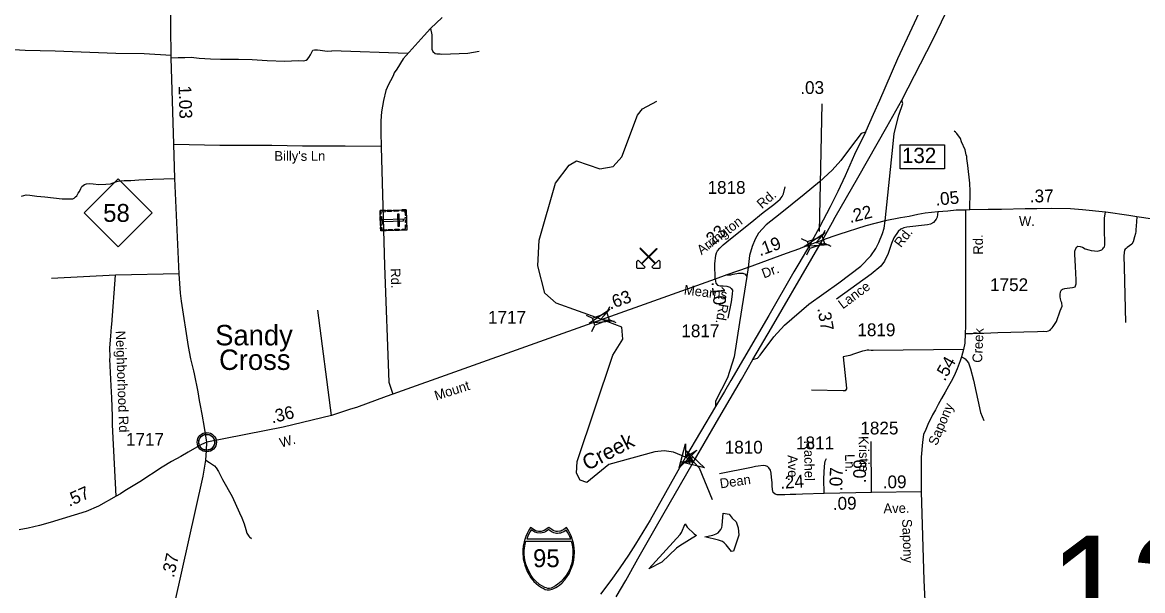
# Model space of a CAD drawing. Extents: x 2220236 to 2384410, y 720751 to 894131.
# Drawn here: x 2310413 to 2321364, y 782328 to 787885 of the extents above; entities that cross this region are included whole.
import ezdxf

# ---------------------------------------------------------------- set-up
doc = ezdxf.new("R2010")
doc.units = 0
doc.layers.add('Default', color=7, linetype='Continuous')

msp = doc.modelspace()

# ---------------------------------------------------------------- linework, layer by layer
at = {"layer": 'Default'}
for p, q in [((2314179, 787582), (2313439, 787606)), ((2318204, 785839), (2318230, 787089)), ((2318231, 785790), (2318262, 785853)), ((2318027, 785771), (2318089, 785741)), ((2318254, 785725), (2318316, 785695)), ((2318082, 785612), (2318112, 785674)), ((2311323, 785414), (2310698, 785381)), ((2311946, 785426), (2311323, 785414)), ((2313436, 784041), (2313303, 785071)), ((2316127, 785043), (2316157, 785105)), ((2315923, 785021), (2315985, 784992)), ((2316151, 784978), (2316214, 784949)), ((2315980, 784863), (2316009, 784925)), ((2318714, 783287), (2318709, 783787)), ((2316921, 783591), (2316944, 783632)), ((2316930, 783640), (2316928, 783659)), ((2316957, 783625), (2316974, 783633)), ((2316890, 783590), (2316907, 783598)), ((2316937, 783564), (2316935, 783583)), ((2319198, 783295), (2318714, 783287)), ((2318714, 783287), (2318252, 783279))]:
    msp.add_line(p, q, dxfattribs=at)
for points in [[(2321136, 791538), (2321055, 791411), (2321030, 791371), (2320819, 791034), (2320553, 790587), (2320307, 790180), (2320046, 789739), (2319894, 789466), (2319698, 789092), (2319507, 788713), (2319271, 788179), (2318968, 787528), (2318793, 787120), (2318731, 786983), (2318659, 786822), (2318654, 786812)], [(2319011, 787125), (2319317, 787721), (2319561, 788233), (2319957, 789028), (2320261, 789629), (2320682, 790477), (2320984, 791079), (2321067, 791240), (2321145, 791392)], [(2312216, 783779), (2312192, 783922), (2312170, 784052), (2312156, 784138), (2312146, 784186), (2312130, 784271), (2312096, 784447), (2312088, 784476), (2312061, 784594), (2312038, 784714), (2311969, 785157), (2311960, 785237), (2311946, 785426), (2311904, 786359), (2311894, 786693), (2311869, 787539), (2311869, 787562), (2311848, 789169)], [(2314518, 787933), (2314403, 787824), (2314342, 787757), (2314222, 787626), (2314137, 787527), (2314073, 787429), (2314048, 787392), (2314039, 787362), (2314012, 787312), (2313993, 787276), (2313966, 787220), (2313944, 787122), (2313923, 787009), (2313916, 786923), (2313916, 786815), (2313920, 786665), (2313952, 785508), (2313995, 784366), (2314036, 784250)], [(2314403, 787824), (2314416, 787762), (2314417, 787622), (2314427, 787599), (2314450, 787580), (2314464, 787577), (2314498, 787577), (2314512, 787575), (2314767, 787585), (2314877, 787605)], [(2311869, 787562), (2311604, 787576), (2311326, 787582), (2310733, 787602), (2310440, 787609), (2310276, 787620)], [(2311869, 787539), (2311937, 787541), (2312002, 787543), (2312062, 787545), (2312143, 787534), (2312253, 787528), (2312351, 787524), (2312525, 787526), (2312661, 787522), (2312806, 787511), (2312980, 787505), (2313110, 787511), (2313161, 787509), (2313188, 787515), (2313201, 787526), (2313214, 787541), (2313229, 787568), (2313245, 787600), (2313254, 787613), (2313269, 787617), (2313299, 787617), (2313324, 787613), (2313394, 787602), (2313439, 787606)], [(2317158, 783215), (2317033, 783526), (2316974, 783586), (2316932, 783611), (2316894, 783634), (2316777, 783682), (2316688, 783694), (2316597, 783686), (2316146, 783561), (2315932, 783384), (2315865, 783408), (2315831, 783475), (2315838, 783591), (2316185, 784629), (2316283, 784787), (2316273, 784905), (2316069, 784984), (2315630, 785138), (2315520, 785238), (2315451, 785505), (2315465, 785755), (2315625, 786312), (2315757, 786488), (2315831, 786531), (2316057, 786452), (2316190, 786477), (2316272, 786569), (2316426, 786979), (2316475, 787040), (2316616, 787114)], [(2318236, 785755), (2318333, 785931), (2318360, 785980), (2318579, 786364), (2318864, 786865), (2319011, 787125)], [(2318848, 785943), (2318926, 786697), (2318937, 786798), (2318982, 786976), (2319020, 787093), (2319011, 787125)], [(2318654, 786812), (2318613, 786798), (2318507, 786662), (2318413, 786533), (2318328, 786438), (2318207, 786325), (2318057, 786201), (2317821, 786011), (2317685, 785905), (2317610, 785822), (2317577, 785764), (2317547, 785692), (2317522, 785604), (2317508, 785489)], [(2318654, 786812), (2318549, 786592), (2318457, 786384), (2318386, 786230), (2318311, 786081), (2318204, 785883), (2318110, 785708)], [(2319674, 786053), (2319678, 786234), (2319675, 786311), (2319657, 786485), (2319646, 786553), (2319646, 786573), (2319638, 786589), (2319628, 786637), (2319595, 786718), (2319584, 786750), (2319548, 786798), (2319536, 786810), (2319521, 786820)], [(2311894, 786693), (2312343, 786685), (2312853, 786685), (2313151, 786678), (2313568, 786678), (2313919, 786674)], [(2310405, 786184), (2310449, 786197), (2310485, 786194), (2310556, 786184), (2310634, 786179), (2310801, 786160), (2310908, 786160), (2310919, 786167), (2310934, 786179), (2310946, 786190), (2310960, 786214), (2310972, 786231), (2310983, 786260), (2310995, 786281), (2311020, 786298), (2311039, 786306), (2311070, 786310), (2311105, 786307), (2311161, 786301), (2311229, 786303), (2311276, 786306), (2311300, 786315), (2311327, 786325), (2311349, 786333), (2311408, 786337), (2311474, 786340), (2311551, 786345), (2311687, 786350), (2311904, 786359)], [(2317184, 785375), (2317182, 785522), (2317191, 785607), (2317200, 785631), (2317210, 785652), (2317230, 785676), (2317263, 785711), (2317335, 785767), (2317528, 785921), (2317654, 786024), (2317759, 786103), (2317798, 786136), (2317821, 786157), (2317841, 786183), (2317854, 786208), (2317870, 786276)], [(2319363, 786032), (2319356, 785980), (2319346, 785960), (2319321, 785927), (2319289, 785911), (2319260, 785905), (2319058, 785882), (2319031, 785875), (2318999, 785862), (2318973, 785839), (2318932, 785777), (2318909, 785724), (2318878, 785626), (2318841, 785549), (2318806, 785501), (2318712, 785424), (2318372, 785177)], [(2319363, 786032), (2319240, 786019), (2319167, 786005), (2319081, 785988), (2318997, 785972), (2318848, 785943)], [(2319634, 786049), (2319634, 784915), (2319631, 784843), (2319626, 784748), (2319612, 784686), (2319595, 784614), (2319581, 784575), (2319572, 784548), (2319551, 784498), (2319531, 784451), (2319506, 784395), (2319467, 784327), (2319434, 784268), (2319398, 784205), (2319366, 784147), (2319339, 784095), (2319311, 784046), (2319293, 784011), (2319278, 783980), (2319266, 783953), (2319245, 783903), (2319223, 783856), (2319211, 783779), (2319200, 783632), (2319198, 783372), (2319198, 783295)], [(2319634, 786049), (2319542, 786048), (2319460, 786040), (2319363, 786032)], [(2321598, 785940), (2321307, 785982), (2321229, 785995), (2321006, 786029), (2321000, 786029), (2320775, 786052), (2320658, 786060), (2320475, 786064), (2320330, 786062), (2320216, 786060), (2319986, 786056), (2319854, 786056), (2319674, 786053), (2319634, 786049)], [(2317555, 784587), (2317601, 784602), (2317627, 784629), (2317760, 784811), (2317863, 784923), (2318100, 785129), (2318393, 785337), (2318610, 785501), (2318707, 785602), (2318756, 785673), (2318785, 785732), (2318820, 785819), (2318838, 785872), (2318848, 785943)], [(2318848, 785943), (2318660, 785896), (2318393, 785812), (2318355, 785799), (2318335, 785792), (2318236, 785755)], [(2319631, 784843), (2319655, 784841), (2319701, 784841), (2319811, 784846), (2319948, 784853), (2320202, 784858), (2320337, 784862), (2320391, 784865), (2320422, 784863), (2320445, 784868), (2320459, 784875), (2320467, 784884), (2320481, 784897), (2320491, 784912), (2320523, 784961), (2320559, 785065), (2320577, 785110), (2320576, 785143), (2320569, 785156), (2320560, 785181), (2320557, 785202), (2320557, 785225), (2320562, 785249), (2320571, 785268), (2320581, 785275), (2320603, 785283), (2320628, 785285), (2320680, 785293), (2320704, 785300), (2320709, 785310), (2320713, 785329), (2320714, 785366), (2320709, 785496), (2320702, 785619), (2320702, 785646), (2320711, 785673), (2320721, 785688), (2320731, 785697), (2320753, 785693), (2320775, 785687), (2320801, 785671), (2320838, 785660), (2320860, 785655), (2320894, 785651), (2320922, 785649), (2320946, 785653), (2320966, 785661), (2320976, 785671), (2320983, 785680), (2320990, 785690), (2320995, 785710), (2320995, 785749), (2320990, 785834), (2320990, 785929), (2320993, 785973), (2321000, 786029)], [(2321307, 785982), (2321302, 785893), (2321299, 785858), (2321297, 785841), (2321295, 785819), (2321286, 785786), (2321271, 785739), (2321258, 785715), (2321235, 785699), (2321213, 785682), (2321203, 785675), (2321193, 785668), (2321187, 785658), (2321184, 785634), (2321180, 785598), (2321185, 785490), (2321197, 784950)], [(2318110, 785708), (2318003, 785528), (2317954, 785444), (2317711, 785019), (2317340, 784382), (2317276, 784274), (2317188, 784127)], [(2318110, 785708), (2318024, 785676), (2318009, 785671), (2317881, 785625), (2317508, 785489)], [(2317555, 784587), (2317735, 784897), (2318131, 785576), (2318236, 785755)], [(2318236, 785755), (2318163, 785728), (2318110, 785708)], [(2317508, 785489), (2317301, 785417)], [(2317508, 785489), (2317494, 785399)], [(2311331, 783252), (2311296, 783883), (2311295, 783953), (2311295, 784033), (2311289, 784212), (2311280, 784332), (2311269, 784592), (2311271, 784612), (2311268, 784702), (2311279, 784816), (2311284, 784908), (2311288, 784930), (2311323, 785414)], [(2317184, 785375), (2316070, 784977)], [(2317301, 785417), (2317184, 785375)], [(2317184, 785375), (2317192, 785334), (2317207, 785314), (2317233, 785308), (2317265, 785308), (2317301, 785305), (2317328, 785295), (2317343, 785283), (2317354, 785266), (2317352, 785226), (2317343, 785151), (2317311, 784992)], [(2317494, 785399), (2317425, 784951), (2317371, 784615), (2317306, 784408), (2317188, 784179), (2317188, 784127)], [(2317301, 785417), (2317340, 785416), (2317363, 785422), (2317415, 785433), (2317456, 785432), (2317478, 785422), (2317494, 785399)], [(2316070, 784977), (2314036, 784250)], [(2318438, 784613), (2318471, 784309), (2318469, 784301), (2318455, 784283), (2318437, 784281), (2318127, 784288)], [(2319612, 784686), (2318729, 784676), (2318711, 784676), (2318687, 784680), (2318673, 784679), (2318647, 784673), (2318625, 784671), (2318547, 784644), (2318502, 784626), (2318438, 784613)], [(2319595, 784614), (2319621, 784601), (2319631, 784594), (2319644, 784577), (2319662, 784555), (2319682, 784498), (2319711, 784385), (2319779, 784071), (2319811, 783992)], [(2316971, 783579), (2317222, 784015), (2317442, 784392), (2317555, 784587)], [(2314036, 784250), (2313970, 784225), (2313679, 784120), (2313620, 784103), (2313543, 784075), (2313436, 784041), (2312964, 783925), (2312216, 783779)], [(2317188, 784127), (2316894, 783634)], [(2312216, 783779), (2312165, 783758), (2312034, 783681), (2311963, 783638), (2311872, 783590), (2311780, 783535), (2311562, 783393), (2311416, 783302), (2311372, 783274), (2311331, 783252), (2311156, 783155), (2311038, 783101), (2310918, 783065), (2310685, 782995), (2310581, 782965), (2310471, 782938), (2310381, 782922)], [(2311831, 781885), (2312182, 783446), (2312208, 783605), (2312212, 783698), (2312216, 783779)], [(2316894, 783634), (2316550, 783017), (2316408, 782783), (2316337, 782674), (2316255, 782551), (2316165, 782425), (2316065, 782292)], [(2312208, 783605), (2312242, 783579), (2312291, 783549), (2312309, 783527), (2312330, 783492), (2312369, 783413), (2312463, 783248), (2312536, 783089), (2312558, 783039), (2312580, 782982), (2312596, 782924), (2312607, 782890), (2312626, 782861), (2312634, 782853), (2312652, 782838)], [(2316217, 782268), (2316311, 782425), (2316429, 782637), (2316612, 782959), (2316971, 783579)], [(2318252, 783279), (2318040, 783271), (2317975, 783268), (2317919, 783267), (2317867, 783263), (2317845, 783263), (2317822, 783265), (2317791, 783263), (2317772, 783272), (2317754, 783287), (2317746, 783318), (2317744, 783352), (2317742, 783384), (2317737, 783434), (2317732, 783477), (2317725, 783504), (2317711, 783530), (2317698, 783542), (2317677, 783548), (2317654, 783552), (2317607, 783546), (2317581, 783541), (2317540, 783533), (2317229, 783469)], [(2318252, 783279), (2318247, 783420), (2318253, 783546), (2318261, 783593), (2318275, 783621)], [(2319198, 783295), (2319225, 782429), (2319240, 782158), (2319247, 782077), (2319265, 782001), (2319289, 781927), (2319302, 781894), (2319325, 781845), (2319352, 781796), (2319405, 781720), (2319421, 781699), (2319449, 781663), (2319469, 781638), (2319516, 781582)], [(2317344, 782709), (2317294, 782775), (2317275, 782795), (2317258, 782807), (2317239, 782816), (2317219, 782821), (2317083, 782852), (2317162, 782869), (2317197, 782882), (2317214, 782894), (2317229, 782909), (2317241, 782926), (2317250, 782945), (2317255, 782965), (2317263, 783084), (2317324, 783076), (2317352, 783036), (2317390, 783000), (2317410, 782941), (2317416, 782871), (2317365, 782712), (2317344, 782709)], [(2316537, 782541), (2316843, 782876), (2316858, 782897), (2316892, 782981), (2316911, 782949), (2316979, 782883), (2317002, 782866), (2316840, 782766), (2316806, 782744), (2316663, 782605), (2316537, 782541)]]:
    msp.add_lwpolyline(points, dxfattribs=at)
for points in [[(2318994, 786687), (2319429, 786687), (2319429, 786454), (2318994, 786454)], [(2311016, 786023), (2311349, 786356), (2311682, 786023), (2311349, 785690)], [(2314164, 786053), (2314171, 785854), (2313916, 785845), (2313910, 786044)], [(2313911, 786011), (2313922, 786011), (2313922, 786033), (2313962, 786035), (2313962, 786046), (2313910, 786044)], [(2313980, 786047), (2314023, 786048), (2314023, 786037), (2313980, 786035)], [(2314047, 786049), (2314090, 786050), (2314090, 786039), (2314047, 786037)], [(2314121, 786051), (2314121, 786040), (2314153, 786041), (2314155, 786001), (2314166, 786001), (2314164, 786053)], [(2313923, 785987), (2313926, 785902), (2313915, 785902), (2313912, 785987)], [(2314139, 785943), (2314138, 785962), (2313935, 785955), (2313936, 785936)], [(2314097, 786010), (2314079, 786009), (2314083, 785891), (2314101, 785892)], [(2314167, 785979), (2314168, 785927), (2314157, 785927), (2314155, 785978)], [(2313915, 785878), (2313927, 785879), (2313928, 785857), (2313968, 785858), (2313968, 785847), (2313916, 785845)], [(2313988, 785859), (2314032, 785860), (2314032, 785849), (2313989, 785848)], [(2314054, 785861), (2314097, 785863), (2314098, 785851), (2314055, 785850)], [(2314128, 785852), (2314127, 785864), (2314159, 785865), (2314158, 785905), (2314169, 785906), (2314171, 785854)], [(2318301, 785709), (2318057, 785693), (2318260, 785829), (2318173, 785732)], [(2318089, 785741), (2318231, 785791), (2318255, 785724), (2318112, 785674)], [(2316598, 785525), (2316603, 785530), (2316455, 785677), (2316450, 785672)], [(2316470, 785522), (2316465, 785527), (2316612, 785675), (2316617, 785670)], [(2316420, 785483), (2316420, 785545), (2316433, 785559), (2316501, 785491), (2316487, 785478), (2316425, 785478)], [(2316647, 785485), (2316647, 785548), (2316634, 785561), (2316566, 785494), (2316580, 785480), (2316642, 785480)], [(2316198, 784963), (2315955, 784943), (2316155, 785081), (2316069, 784984)], [(2315985, 784992), (2316127, 785043), (2316151, 784977), (2316009, 784925)], [(2312138, 783791), (2312139, 783797), (2312141, 783804), (2312144, 783811), (2312147, 783816), (2312150, 783822), (2312154, 783827), (2312158, 783832), (2312162, 783836), (2312168, 783841), (2312173, 783845), (2312178, 783847), (2312183, 783850), (2312189, 783852), (2312194, 783854), (2312199, 783855), (2312203, 783856), (2312208, 783857), (2312214, 783857), (2312218, 783857), (2312224, 783856), (2312229, 783856), (2312234, 783855), (2312239, 783853), (2312244, 783851), (2312251, 783848), (2312257, 783845), (2312262, 783841), (2312267, 783837), (2312270, 783834), (2312275, 783830), (2312278, 783825), (2312282, 783821), (2312285, 783816), (2312287, 783810), (2312289, 783805), (2312291, 783800), (2312292, 783796), (2312293, 783790), (2312294, 783785), (2312294, 783779), (2312294, 783773), (2312293, 783768), (2312292, 783762), (2312291, 783756), (2312289, 783750), (2312286, 783745), (2312283, 783739), (2312280, 783734), (2312277, 783729), (2312272, 783724), (2312267, 783719), (2312262, 783715), (2312257, 783712), (2312253, 783709), (2312246, 783706), (2312239, 783703), (2312233, 783702), (2312226, 783701), (2312222, 783700), (2312217, 783700), (2312212, 783700), (2312207, 783700), (2312202, 783701), (2312196, 783702), (2312191, 783704), (2312186, 783705), (2312181, 783707), (2312178, 783710), (2312171, 783714), (2312165, 783718), (2312160, 783723), (2312156, 783727), (2312153, 783731), (2312150, 783736), (2312146, 783743), (2312144, 783746), (2312142, 783750), (2312140, 783758), (2312138, 783765), (2312137, 783771), (2312137, 783777), (2312137, 783782), (2312137, 783788)], [(2317005, 783702), (2316835, 783527), (2316894, 783764), (2316894, 783634)], [(2316906, 783696), (2317081, 783527), (2316844, 783586), (2316974, 783586)], [(2316935, 783583), (2316958, 783624), (2316930, 783640), (2316907, 783598)], [(2315558, 782334), (2315567, 782334), (2315580, 782337), (2315593, 782341), (2315607, 782347), (2315627, 782359), (2315644, 782369), (2315664, 782382), (2315690, 782405), (2315716, 782433), (2315739, 782464), (2315757, 782493), (2315773, 782526), (2315786, 782557), (2315797, 782592), (2315804, 782626), (2315808, 782662), (2315810, 782702), (2315807, 782746), (2315800, 782792), (2315792, 782820), (2315781, 782854), (2315772, 782876), (2315752, 782914), (2315733, 782944), (2315706, 782925), (2315688, 782915), (2315677, 782910), (2315666, 782908), (2315645, 782906), (2315632, 782906), (2315621, 782909), (2315610, 782911), (2315602, 782915), (2315558, 782944), (2315514, 782915), (2315504, 782911), (2315495, 782909), (2315486, 782906), (2315471, 782906), (2315459, 782906), (2315447, 782908), (2315438, 782910), (2315427, 782915), (2315382, 782944), (2315364, 782918), (2315350, 782893), (2315335, 782857), (2315325, 782829), (2315318, 782806), (2315310, 782764), (2315306, 782728), (2315305, 782702), (2315310, 782637), (2315317, 782603), (2315324, 782575), (2315348, 782515), (2315366, 782481), (2315381, 782457), (2315403, 782430), (2315414, 782417), (2315459, 782378), (2315489, 782357), (2315513, 782345), (2315524, 782340), (2315542, 782335)], [(2315387, 782923), (2315377, 782906), (2315364, 782883), (2315354, 782860), (2315343, 782833), (2315775, 782833), (2315765, 782856), (2315754, 782878), (2315743, 782899), (2315729, 782919), (2315705, 782903), (2315687, 782895), (2315673, 782890), (2315661, 782888), (2315643, 782886), (2315634, 782887), (2315608, 782892), (2315591, 782900), (2315574, 782911), (2315561, 782924), (2315526, 782903), (2315511, 782896), (2315494, 782892), (2315475, 782889), (2315445, 782892), (2315422, 782900), (2315402, 782911)], [(2315777, 782812), (2315782, 782800), (2315788, 782773), (2315792, 782752), (2315795, 782728), (2315794, 782687), (2315792, 782644), (2315788, 782619), (2315783, 782596), (2315776, 782571), (2315764, 782537), (2315748, 782508), (2315728, 782476), (2315707, 782448), (2315698, 782437), (2315680, 782418), (2315648, 782392), (2315624, 782375), (2315596, 782358), (2315582, 782352), (2315565, 782348), (2315551, 782349), (2315535, 782354), (2315521, 782357), (2315492, 782373), (2315468, 782389), (2315428, 782422), (2315407, 782447), (2315387, 782476), (2315369, 782506), (2315350, 782546), (2315336, 782586), (2315326, 782629), (2315320, 782682), (2315319, 782714), (2315321, 782745), (2315324, 782761), (2315328, 782781), (2315336, 782812)]]:
    msp.add_lwpolyline(points, close=True, dxfattribs=at)
for centre, radius in [((2312216, 783779), 94.3), ((2312215, 783779), 76.7)]:
    msp.add_circle(centre, radius, dxfattribs=at)

# ---------------------------------------------------------------- texts
for s, height, rotation, p in [('1.03', 125, 271.6551, (2311940, 787266)), ('.03', 125, 0.4156, (2318018, 787184)), ('.37', 125, 0.512, (2320262, 786124)), ('Rd.', 95, 40.8209, (2317643, 786057)), ('.05', 125, 5.444, (2319344, 786092)), ('.22', 125, 13.9415, (2318505, 785922)), ('Arrington', 95, 37.2561, (2317052, 785607)), ('W.', 95, 359.484, (2320155, 785895)), ('.23', 125, 41.0169, (2317127, 785669)), ('Rd.', 95, 52.2754, (2319002, 785676)), ('.19', 125, 19.9594, (2317623, 785597)), ('Rd.', 95, 90.3228, (2319803, 785614)), ('Dr.', 95, 20.7651, (2317662, 785380)), ('Rd.', 95, 271.9669, (2314013, 785479)), ('Mearns', 95, 353.0214, (2316876, 785225)), ('.10', 125, 275.4792, (2317149, 785346)), ('Lance', 95, 36.584, (2318433, 785077)), ('.63', 125, 19.6705, (2316159, 785075)), ('Rd.', 95, 260.3415, (2317223, 785139)), ('.37', 125, 280.1706, (2318184, 785088)), ('Neighborhood Rd', 95, 271.994, (2311325, 784868)), ('Creek', 95, 87.2033, (2319794, 784554)), ('.54', 125, 60.5042, (2319430, 784369)), ('Mount', 95, 17.8672, (2314459, 784186)), ('.36', 125, 13.8717, (2312855, 783962)), ('Sapony', 95, 67.1965, (2319352, 783739)), ('W.', 95, 15.8728, (2312943, 783725)), ('Creek', 150, 27.6816, (2315936, 783497)), ('Rachel', 95, 270.9903, (2318054, 783795)), ('Kristie', 95, 271.3869, (2318588, 783838)), ('Ave.', 95, 270.9903, (2317895, 783653)), ('Ln.', 95, 271.3869, (2318455, 783662)), ('.07', 125, 88.6308, (2318427, 783300)), ('.09', 125, 88.6308, (2318658, 783377)), ('Dean', 95, 8.3654, (2317238, 783327)), ('.24', 125, 3.7778, (2317825, 783322)), ('.09', 125, 0.9214, (2318825, 783327)), ('.57', 125, 23.766, (2310871, 783146)), ('.09', 125, 0.9903, (2318337, 783117)), ('Ave.', 95, 1.1195, (2318832, 783084)), ('Sapony', 95, 271.9038, (2319013, 783027)), ('.37', 125, 77.332, (2311894, 782449))]:
    msp.add_text(s, height=height, rotation=rotation, dxfattribs=at).set_placement(p)
for s, height, p in [("Billy's Ln", 95, (2312877, 786531)), ('132', 150, (2319012, 786509)), ('1818', 125, (2317111, 786208)), ('58', 175, (2311203, 785934)), ('1752', 125, (2319873, 785257)), ('1717', 125, (2314965, 784938)), ('Sandy', 200, (2312298, 784726)), ('1819', 125, (2318576, 784816)), ('1817', 125, (2316855, 784806)), ('Cross', 200, (2312336, 784486)), ('1825', 125, (2318605, 783855)), ('1717', 125, (2311426, 783744)), ('1810', 125, (2317279, 783668)), ('1811', 125, (2317976, 783710)), ('128', 1066.3, (2320448, 781800)), ('95', 175, (2315405, 782557))]:
    msp.add_text(s, height=height, dxfattribs=at).set_placement(p)

doc.saveas('drawing.dxf')
